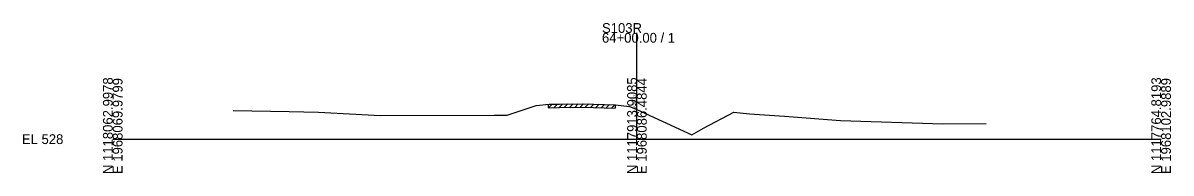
# Model space of a CAD drawing. Extents: x 974 to 1303, y 990 to 10019.
# Drawn here: x 974.3 to 1302.8, y 6490.3 to 6533.2 of the extents above; entities that cross this region are included whole.
import ezdxf

# ---------------------------------------------------------------- set-up
doc = ezdxf.new("R2010")
doc.units = 0
for name, color, linetype in [('Level 10', 7, 'Continuous'), ('Level 60', 7, 'Continuous'), ('Level 61', 7, 'Continuous'), ('Level 63', 7, 'Continuous')]:
    doc.layers.add(name, color=color, linetype=linetype)

msp = doc.modelspace()

# ---------------------------------------------------------------- linework, layer by layer
at = {"layer": 'Level 60'}
for p, q in [((1113.73, 6507.13), (1121.14, 6509.61)), ((1121.14, 6509.61), (1124.85, 6509.98)), ((1124.85, 6509.98), (1127.88, 6510.03)), ((1127.88, 6510.03), (1134.32, 6510.13)), ((1134.32, 6510.13), (1143.91, 6509.83)), ((1143.91, 6509.83), (1147.85, 6509.34)), ((1147.85, 6509.34), (1148.18, 6509.29)), ((1148.18, 6509.29), (1150, 6508.47)), ((1150, 6508.47), (1165.71, 6501.27)), ((1034.45, 6508.16), (1050.53, 6507.92)), ((1050.53, 6507.92), (1058.89, 6507.68)), ((1058.89, 6507.68), (1076.58, 6506.78)), ((1076.58, 6506.78), (1109.15, 6506.91)), ((1109.15, 6506.91), (1112.86, 6506.89)), ((1112.86, 6506.89), (1113.73, 6507.13)), ((1169.06, 6503.19), (1177.76, 6507.76)), ((1177.76, 6507.76), (1182.2, 6507.25)), ((1182.2, 6507.25), (1192.24, 6506.54)), ((1192.24, 6506.54), (1208.24, 6505.31)), ((1208.24, 6505.31), (1237.57, 6504.43)), ((1165.71, 6501.27), (1169.06, 6503.19)), ((1237.57, 6504.43), (1249.92, 6504.48))]:
    msp.add_line(p, q, dxfattribs=at)
at = {"layer": 'Level 61'}
for p, q in [((1124.72, 6508.96), (1125.75, 6509.99)), ((1124.72, 6508.96), (1124.72, 6509.96)), ((1124.72, 6508.96), (1124.85, 6508.98)), ((1124.85, 6508.98), (1127.88, 6509.03)), ((1126.22, 6509), (1127.23, 6510.02)), ((1127.72, 6509.02), (1128.73, 6510.04)), ((1127.88, 6509.03), (1134.32, 6509.13)), ((1129.22, 6509.05), (1130.23, 6510.07)), ((1130.72, 6509.07), (1131.73, 6510.09)), ((1132.22, 6509.1), (1133.23, 6510.12)), ((1133.72, 6509.12), (1134.72, 6510.12)), ((1134.32, 6509.13), (1143.79, 6508.84)), ((1135.22, 6509.11), (1136.19, 6510.08)), ((1136.72, 6509.06), (1137.69, 6510.03)), ((1138.22, 6509.01), (1139.19, 6509.98)), ((1139.72, 6508.97), (1140.69, 6509.93)), ((1141.22, 6508.92), (1142.19, 6509.89)), ((1142.72, 6508.87), (1143.69, 6509.84)), ((1143.79, 6509.84), (1143.79, 6508.84))]:
    msp.add_line(p, q, dxfattribs=at)
at = {"layer": 'Level 63'}
for p, q in [((1150, 6500), (1150, 6530.4)), ((1000, 6500), (1150, 6500)), ((1150, 6500), (1300, 6500))]:
    msp.add_line(p, q, dxfattribs=at)

# ---------------------------------------------------------------- texts
at = {"layer": 'Level 10'}
msp.add_text('536.47', height=0.9, rotation=90, dxfattribs=at).set_placement((1149.95, 6508.97))
at = {"layer": 'Level 63'}
for s, p in [('S103R', (1140, 6530.4)), ('64+00.00 / 1', (1140, 6527.6)), ('EL 528', (974, 6498.6))]:
    msp.add_text(s, height=2.8, dxfattribs=at).set_placement(p)
for s, p in [('N 1118062.9978', (1000, 6490)), ('E 1968069.9799', (1002.8, 6490)), ('N 1117913.9085', (1150, 6490)), ('E 1968086.4844', (1152.8, 6490)), ('N 1117764.8193', (1300, 6490)), ('E 1968102.9889', (1302.8, 6490))]:
    msp.add_text(s, height=2.8, rotation=90, dxfattribs=at).set_placement(p)

doc.saveas('drawing.dxf')
